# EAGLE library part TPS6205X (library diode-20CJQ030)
Ti's TPS6205x 800-mA SYNCHRONOUS STEP-DOWN CONVERTER Description: The TPS6205x devices are a family of high-efficiency synchronous step-down dc/dc converters ideally suited for systems powered from a 1-cell or 2-cell Li-Ion battery or from a 3-cell to 5-cell NiCd, NiMH, or alkaline battery. The TPS62050 is a synchronous PWM converter with integrated N-channel and P-channel power MOSFET switches. Synchronous rectification increases efficiency and reduces external component count. To achieve highest efficiency over a wide load current range, the converter enters a power-saving pulse-frequency modulation (PFM) mode at light load currents. Operating frequency is typically 850 kHz, allowing the use of small inductor and capacitor values. The device can be synchronized to an external clock signal in the range of 600 kHz to 1.2 MHz. For low noise operation, the converter can be programmed into forced-fixed frequency in PWM mode. In shutdown mode, the current consumption is reduced to less than 2 µA. The TPS6205x is available in the 10-pin (DGS) micro-small outline package (MSOP) and operates over an free air temperature range of -40°C to 85°C. Features: High-Efficiency Synchronous Step-Down Converter With up to 95% Efficiency 12-µA Quiescent Current (Typ) 2.7-V to 10-V Operating Input Voltage Range Adjustable Output Voltage Range From 0.7 V to 6 V Fixed Output Voltage Options Available in 1.5 V, 1.8 V, and 3.3 V Synchronizable to External Clock Signal up to 1.2 MHz High Efficiency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
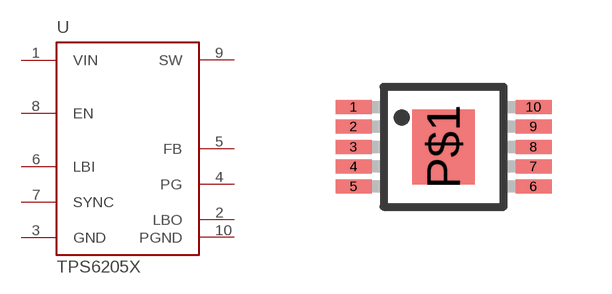
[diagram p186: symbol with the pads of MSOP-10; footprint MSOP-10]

Designator prefix U

## TPS6205X  [MSOP-10]
1  VIN  pwr
2  LBO  pas
3  GND  pwr
4  PG
5  FB
6  LBI  pas
7  SYNC  in
8  EN  in
9  SW
10  PGND  pwr

## Footprint MSOP-10 (pad centres in mm)
Ti's MSOP-10 with PowerPAD
smd 0.9 x 0.35: 1 -2.25,1; 2 -2.25,0.51; 3 -2.25,0; 4 -2.25,-0.49; 5 -2.25,-0.99; 6 2.25,-0.99; 7 2.25,-0.49; 8 2.25,0; 9 2.25,0.51; 10 2.25,1
smd 1.57 x 1.88: P$1 0,0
